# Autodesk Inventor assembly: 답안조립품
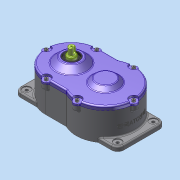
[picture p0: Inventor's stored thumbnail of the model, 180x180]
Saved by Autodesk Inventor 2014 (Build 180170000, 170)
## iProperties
Created: 2025-09
Part Number: 답안조립품
Document SubType Name: Assembly
Designer: dg
Author: dg
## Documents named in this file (19)
- C:\Users\dg\Desktop\750903V1006\답안조립품.iam
- C:\Users\dg\Desktop\750903V1006\본체.ipt
- C:\Users\dg\Desktop\750903V1006\가져온 구성요소\6각 구멍붙이 볼트 M4x10\6각 구멍붙이 볼트 M4x10.ipt
- C:\Users\dg\Desktop\750903V1006\가져온 구성요소\6각 구멍붙이 볼트 M6x12\6각 구멍붙이 볼트 M6x12.ipt
- C:\Users\dg\Desktop\750903V1006\가져온 구성요소\구동 축\구동 축.ipt
- C:\Users\dg\Desktop\750903V1006\가져온 구성요소\구동 휠\구동 휠.ipt
- C:\Users\dg\Desktop\750903V1006\가져온 구성요소\깊은 홈 볼 베어링 6904\깊은 홈 볼 베어링 6904.ipt
- C:\Users\dg\Desktop\750903V1006\가져온 구성요소\스러스트 볼 베어링 51102\스러스트 볼 베어링 51102.ipt
- C:\Users\dg\Desktop\750903V1006\가져온 구성요소\스프링 와셔 M3\스프링 와셔 M3.ipt
- C:\Users\dg\Desktop\750903V1006\가져온 구성요소\슬롯 축\슬롯 축.ipt
- C:\Users\dg\Desktop\750903V1006\가져온 구성요소\슬롯\슬롯.ipt
- C:\Users\dg\Desktop\750903V1006\가져온 구성요소\어댑터\어댑터.ipt
- C:\Users\dg\Desktop\750903V1006\가져온 구성요소\오일 실 20 35 8\오일 실 20 35 8.ipt
- C:\Users\dg\Desktop\750903V1006\가져온 구성요소\평행 키 6x6x14\평행 키 6x6x14.ipt
- C:\Users\dg\Desktop\750903V1006\가져온 구성요소\커버\커버.ipt
- C:\Users\dg\Desktop\750903V1006\가져온 구성요소\칼라\칼라.ipt
- C:\Users\dg\Desktop\750903V1006\가져온 구성요소\캠 플로워\캠 플로워.ipt
- C:\Users\dg\Desktop\750903V1006\가져온 구성요소\평 와셔 M3\평 와셔 M3.ipt
- C:\Users\dg\Desktop\750903V1006\가져온 구성요소\육각 너트 M3\육각 너트 M3.ipt
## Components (9 placed, 4 different names)
1. 6각 구멍붙이 볼트 M4x10:1
2. 6각 구멍붙이 볼트 M6x12:1
3. 구동 축:1
4. 구동 휠:1
5. 6각 구멍붙이 볼트 M4x10:2
6. 6각 구멍붙이 볼트 M4x10:3
7. 6각 구멍붙이 볼트 M4x10:4
8. 6각 구멍붙이 볼트 M4x10:5
9. 6각 구멍붙이 볼트 M4x10:6
